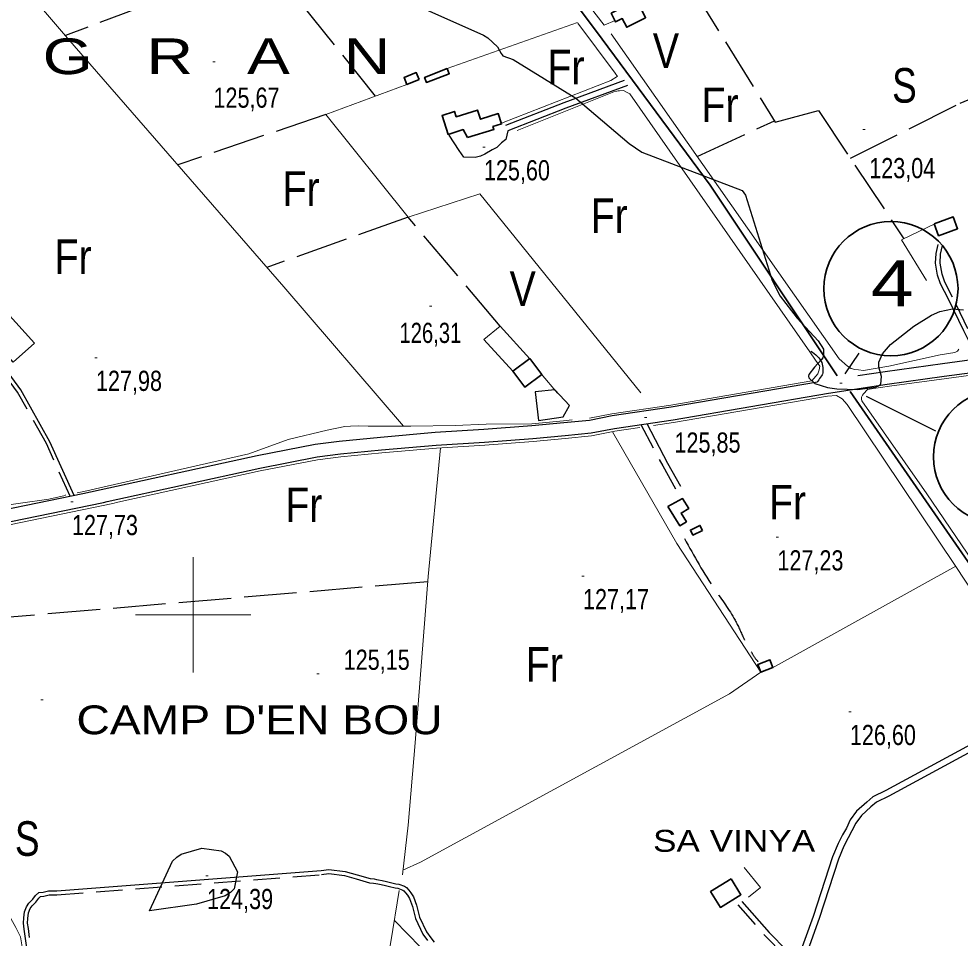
# Model space of a CAD drawing. Extents: x 483847 to 488453, y 4383581 to 4386795.
# Drawn here: x 486424.4 to 486832.5, y 4384859.8 to 4385258.4 of the extents above; entities that cross this region are included whole.
import ezdxf
from ezdxf.enums import TextEntityAlignment as Align

# ---------------------------------------------------------------- set-up
doc = ezdxf.new("R2010")
doc.units = 0
doc.header["$LTSCALE"] = 3.8
doc.linetypes.add('LONG_DASHED', pattern=[7.5, 6, -1.5])
doc.linetypes.add('MEDIUM_DASHED', pattern=[4.5, 3, -1.5])
for name, color, linetype, lineweight in [('1', 7, 'Continuous', 13), ('13', 7, 'Continuous', 25), ('21', 7, 'Continuous', 25), ('25', 7, 'LONG_DASHED', 25), ('36', 7, 'Continuous', 25), ('38', 7, 'Continuous', 25), ('47', 7, 'Continuous', 35), ('51', 7, 'Continuous', 13), ('6', 7, 'Continuous', 35), ('7', 7, 'Continuous', 13), ('8', 7, 'Continuous', 25)]:
    doc.layers.add(name, color=color, linetype=linetype, lineweight=lineweight)
doc.layers.add('31', color=7, linetype='Continuous')
doc.layers.add('5', color=7, linetype='Continuous')

msp = doc.modelspace()

# ---------------------------------------------------------------- linework, layer by layer
at = {"layer": '1'}
for p, q in [((486500, 4385025), (486500, 4384975)), ((486475, 4385000), (486525, 4385000))]:
    msp.add_line(p, q, dxfattribs=at)
at = {"layer": '21'}
for points in [[(486422.01, 4385109.58), (486409.88, 4385123.11), (486419.02, 4385131.31), (486431.15, 4385117.78)], [(486649.69, 4385084.33), (486660.44, 4385085.83), (486663.06, 4385090.75), (486656.7, 4385097.52), (486648.29, 4385096.74)]]:
    msp.add_lwpolyline(points, close=True, dxfattribs=at)
at = {"layer": '25'}
for p, q in [((486534.31, 4385284.81), (486444.57, 4385251.17)), ((486557.49, 4385216.97), (486493.3, 4385195.11)), ((486718.49, 4385198.73), (486751.94, 4385214.25)), ((486593.17, 4385172.49), (486531.98, 4385150.63)), ((486633.09, 4385125.17), (486593.17, 4385172.49)), ((486601.64, 4385014.36), (486335.46, 4384991.81))]:
    msp.add_line(p, q, dxfattribs=at)
for points in [[(486579.03, 4385224.91), (486531.89, 4385283.89), (486621.26, 4385317.93)], [(486715.71, 4385272.63), (486752.31, 4385213.65), (486771.07, 4385218.71), (486808.04, 4385163.09)], [(486784.88, 4385197.95), (486832.42, 4385221.88), (486887.14, 4385244.21), (486926.28, 4385257.91), (486977.19, 4385187.02), (487015.51, 4385200.95), (487056.56, 4385139.53)]]:
    msp.add_lwpolyline(points, dxfattribs=at)
at = {"layer": '36'}
for points in [[(486788.13, 4385103.8), (486799.99, 4385105.59), (486824.76, 4385108.99), (486852.42, 4385112.73), (486879.93, 4385115.94), (486915.02, 4385120.69), (486950.06, 4385124.99), (487008.15, 4385132.49), (487066.94, 4385140.05), (487152.14, 4385151.05), (487219.98, 4385161.17), (487294.79, 4385172.63), (487350, 4385181.14), (487422.16, 4385191.98), (487448.32, 4385195.53)], [(486398.31, 4385035.88), (486461.13, 4385048.69), (486462.73, 4385049.14), (486528.81, 4385063.65), (486553.7, 4385068.46), (486563.83, 4385069.82), (486581.63, 4385071.52), (486605.36, 4385073.58), (486626.31, 4385074.93), (486647.28, 4385076.51), (486661.18, 4385077.81), (486672.55, 4385078.92), (486682.57, 4385080.87), (486708.05, 4385084.63), (486775.37, 4385096.2), (486800.8, 4385100.04), (486825.52, 4385103.44), (486853.12, 4385107.17)], [(486397.22, 4385041.38), (486452.17, 4385052.61), (486452.19, 4385052.58), (486527.68, 4385069.14), (486552.8, 4385074), (486563.2, 4385075.39), (486581.12, 4385077.1), (486604.95, 4385079.16), (486625.92, 4385080.52), (486646.81, 4385082.09), (486660.65, 4385083.38), (486671.74, 4385084.47), (486681.62, 4385086.4), (486707.17, 4385090.17), (486770.61, 4385101.07)]]:
    msp.add_lwpolyline(points, dxfattribs=at)
msp.add_spline([(486767.68, 4385114.39), (486772.5, 4385109.36), (486772.99, 4385106.58), (486772.97, 4385105.38), (486772.81, 4385104.41), (486772.42, 4385103.66), (486770.74, 4385101.28), (486770.61, 4385101.07)], degree=3, dxfattribs=at)
at = {"layer": '38'}
for points in [[(486686.81, 4385231.67), (486660.69, 4385221.99), (486635.41, 4385212.15)], [(486688.29, 4385229.55), (486661.57, 4385219.65), (486636.32, 4385209.82)], [(486636.32, 4385209.82), (486635.52, 4385206.1), (486633.63, 4385204.7), (486631.65, 4385202.7), (486629.6, 4385201.6), (486626.43, 4385199.7), (486624.61, 4385198.82), (486622.28, 4385198.26), (486617.33, 4385198.4), (486615.34, 4385201.28), (486611.01, 4385207.95)], [(486840.18, 4385111.08), (486834.13, 4385123.12), (486827.44, 4385136.94), (486824.03, 4385143.52), (486822.72, 4385147.23), (486821.84, 4385152.44), (486822.06, 4385156.73), (486822.98, 4385160.61)], [(486448.36, 4385051.83), (486437.86, 4385075.04), (486425.24, 4385097.52), (486412.29, 4385115.2), (486404.5, 4385123.67), (486402.79, 4385126.68)], [(486696.61, 4385082.94), (486705.66, 4385065.74), (486711.28, 4385055.77)], [(486871.62, 4384959.34), (486801.55, 4384921.35), (486796.15, 4384918.79), (486793.78, 4384916.77), (486789.64, 4384913.03), (486787.19, 4384909.74), (486785.59, 4384906.31), (486783.89, 4384903.32), (486782.07, 4384899.65), (486779.7, 4384894.15), (486771.31, 4384868.35), (486749.34, 4384806.96), (486719.71, 4384723.87), (486691.28, 4384645.79), (486672.37, 4384593.39), (486657.19, 4384549.7), (486638.22, 4384498.21), (486619.96, 4384444), (486590.17, 4384360.22), (486574.09, 4384315.2)], [(486870.18, 4384961.68), (486800.3, 4384923.8), (486794.64, 4384921.12), (486791.97, 4384918.84), (486787.59, 4384914.89), (486784.82, 4384911.16), (486783.15, 4384907.57), (486781.47, 4384904.61), (486779.57, 4384900.81), (486777.13, 4384895.12), (486768.71, 4384869.24), (486762.14, 4384850.9)], [(486444.14, 4384741.23), (486426.75, 4384863.74), (486426.41, 4384866.31), (486426.52, 4384868.59), (486426.87, 4384871.24), (486427.66, 4384873.46), (486428.76, 4384875.06), (486430.44, 4384876.69), (486431.67, 4384878.33), (486433.02, 4384879.57), (486434.96, 4384879.84), (486437.31, 4384880.35), (486440.85, 4384880.37), (486555.4, 4384889.23), (486558.8, 4384889.64), (486565.88, 4384888.7), (486571.13, 4384887.27), (486576.72, 4384885.63), (486578.43, 4384885.53), (486579.49, 4384885.28), (486580.39, 4384885.12), (486581.89, 4384884.87), (486583.77, 4384884.39), (486585.48, 4384883.92), (486587.87, 4384883.43), (486589.16, 4384883.19), (486591.66, 4384882.32), (486592.53, 4384881.74), (486593.43, 4384880.66), (486594.4, 4384879.51), (486595.45, 4384877.81), (486596.83, 4384874.15), (486598.04, 4384868.97), (486601.15, 4384862.51), (486603.05, 4384859.95), (486604.44, 4384858.06)], [(486737.86, 4384875.75), (486749.72, 4384862.27), (486757.33, 4384854.5), (486759.64, 4384852.87), (486760.9, 4384851.8), (486761.81, 4384851.14), (486762.14, 4384850.9)]]:
    msp.add_lwpolyline(points, dxfattribs=at)
at = {"layer": '38', "linetype": 'MEDIUM_DASHED'}
for points in [[(486842.23, 4385111.35), (486835.88, 4385123.99), (486829.18, 4385137.82), (486825.83, 4385144.3), (486824.62, 4385147.72), (486823.8, 4385152.55), (486824.01, 4385156.45), (486824.88, 4385160.16)], [(486446.65, 4385051.48), (486436.35, 4385074.27), (486423.8, 4385096.6), (486410.98, 4385114.12), (486403.12, 4385122.66), (486401.31, 4385125.85)], [(486694.06, 4385082.57), (486703.53, 4385064.58), (486709.16, 4385054.58)], [(486445.9, 4384741.62), (486428.54, 4384863.99), (486428.22, 4384866.39), (486428.32, 4384868.43), (486428.63, 4384870.82), (486429.28, 4384872.63), (486430.15, 4384873.9), (486431.79, 4384875.5), (486433.01, 4384877.11), (486433.83, 4384877.86), (486435.28, 4384878.07), (486437.5, 4384878.55), (486440.93, 4384878.57), (486555.58, 4384887.43), (486558.79, 4384887.82), (486565.53, 4384886.93), (486570.64, 4384885.54), (486576.41, 4384883.84), (486578.18, 4384883.74), (486579.13, 4384883.52), (486580.08, 4384883.35), (486581.51, 4384883.11), (486583.3, 4384882.65), (486585.06, 4384882.17), (486587.52, 4384881.67), (486588.69, 4384881.45), (486590.85, 4384880.69), (486591.31, 4384880.39), (486592.05, 4384879.5), (486592.93, 4384878.45), (486593.82, 4384877.01), (486595.1, 4384873.63), (486596.33, 4384868.37), (486599.6, 4384861.58), (486601.6, 4384858.88)], [(486736.14, 4384874.25), (486748.04, 4384860.72), (486755.84, 4384852.76), (486758.24, 4384851.06), (486759.5, 4384850), (486760.47, 4384849.3), (486761.35, 4384848.65)]]:
    msp.add_lwpolyline(points, dxfattribs=at)
at = {"layer": '38', "linetype": 'LONG_DASHED'}
msp.add_spline([(486712.96, 4385033.08), (486726.15, 4385010.9), (486734.89, 4384997.72), (486738.53, 4384990.09), (486740.21, 4384986.69), (486742.11, 4384983.59), (486744.47, 4384980.18), (486744.83, 4384979.8)], degree=3, dxfattribs=at)
at = {"layer": '47'}
for points in [[(486696.75, 4385268.7), (486681.25, 4385260.82), (486683.13, 4385257.09), (486686.02, 4385258.55), (486687.93, 4385254.76), (486696.14, 4385258.91), (486694.61, 4385261.91), (486698.89, 4385264.11)], [(486610.15, 4385236.85), (486600.27, 4385233.06), (486601.13, 4385230.83), (486611.01, 4385234.62)], [(486597.93, 4385232.07), (486592.65, 4385229.93), (486591.41, 4385232.99), (486596.69, 4385235.13)], [(486618.88, 4385206.94), (486630.33, 4385210.52), (486629.96, 4385211.7), (486633.67, 4385212.87), (486632.26, 4385217.33), (486624.49, 4385214.87), (486623.21, 4385218.88), (486614, 4385215.95), (486613.24, 4385218.31), (486607.87, 4385216.59), (486610.52, 4385208.31), (486617.09, 4385210.44)], [(486821.24, 4385169.52), (486829.46, 4385172.54), (486831.34, 4385167.42), (486823.12, 4385164.4)], [(486645.94, 4385111.1), (486651.07, 4385104.16), (486643.74, 4385098.75), (486638.61, 4385105.69)], [(486705.8, 4385047.06), (486710.94, 4385038.66), (486713.79, 4385040.41), (486711.49, 4385044.15), (486714.8, 4385046.18), (486712.18, 4385050.43)], [(486720.74, 4385036.57), (486716.63, 4385034.58), (486715.56, 4385036.79), (486719.67, 4385038.78)], [(486751.33, 4384977.15), (486746.09, 4384975.09), (486744.74, 4384978.52), (486749.98, 4384980.58)], [(486733.21, 4384885.57), (486724.28, 4384880.06), (486728.53, 4384873.18), (486737.46, 4384878.69)]]:
    msp.add_lwpolyline(points, close=True, dxfattribs=at)
at = {"layer": '51'}
for p, q in [((486610.15, 4385236.85), (486666.56, 4385256.83)), ((486657.99, 4385096.16), (486650.83, 4385104.5)), ((486751.08, 4384977.06), (486830.66, 4385021.06))]:
    msp.add_line(p, q, dxfattribs=at)
for points in [[(486682.85, 4385257.65), (486678.1, 4385255.69), (486640.68, 4385304.24), (486607.97, 4385346.36), (486584.05, 4385379.27)], [(486171.92, 4385214.4), (486206.85, 4385238.2), (486361.2, 4385348.39), (486445.48, 4385250.09), (486539.31, 4385142.19), (486591.21, 4385081.82)], [(486666.79, 4385256.51), (486682.9, 4385234.82), (486683.9, 4385233.4)], [(486681.2, 4385251.89), (486779.96, 4385111.06), (486783.66, 4385107.85), (486785.3, 4385106.85), (486786.79, 4385106.46), (486788.37, 4385106.21), (486790.61, 4385105.95), (486801.52, 4385107.9), (486823.8, 4385112.68), (486830.19, 4385113.71), (486831.4, 4385114.37), (486831.94, 4385115.26)], [(486683.86, 4385233.46), (486681.06, 4385231.71), (486633.58, 4385213.2)], [(486694.05, 4385096.23), (486624.31, 4385182.62), (486593.17, 4385172.49), (486557.49, 4385216.97), (486592.65, 4385229.93)], [(486640.46, 4385210), (486682.34, 4385226.74), (486683.7, 4385227.09), (486684.22, 4385227.23), (486684.82, 4385227.23), (486686.48, 4385227.35), (486687.89, 4385226.66), (486689.23, 4385225.96), (486767.32, 4385114.01), (486769.82, 4385110.45), (486771.58, 4385107.87), (486771.41, 4385106.3), (486770.78, 4385104.51), (486768.14, 4385101.48)], [(486821.77, 4385169.71), (486807.03, 4385162.59), (486817.96, 4385145.03)], [(486794.1, 4385097.95), (486801.86, 4385099.12), (486826.57, 4385102.52), (486854.16, 4385106.23), (486881.67, 4385109.44), (486916.78, 4385114.2), (486951.8, 4385118.5), (487008.57, 4385125.57)], [(486645.91, 4385111.08), (486633.09, 4385125.17), (486626.03, 4385119.41), (486638.61, 4385105.69)], [(486768.14, 4385101.48), (486707.04, 4385090.97), (486681.49, 4385087.2), (486671.77, 4385085.3)], [(486794.1, 4385097.95), (486792.37, 4385097.67), (486790.54, 4385095.9), (486790.09, 4385095.3), (486789.93, 4385094.93), (486789.7, 4385094.33), (486789.68, 4385093.51), (486789.9, 4385092.76), (486817.99, 4385052.43), (486848.12, 4385008.33), (486858.49, 4384993.48), (486861.43, 4384994.63)], [(486775, 4385094.84), (486708.25, 4385083.37), (486699.5, 4385082.08)], [(486775, 4385094.84), (486778.9, 4385095.16), (486781.36, 4385093.63), (486783.5, 4385091.27), (486830.67, 4385021.04), (486861.8, 4384973.54), (486864.73, 4384968.62), (486865.54, 4384967.19), (486865.53, 4384966.74), (486865.52, 4384965.99), (486865.27, 4384964.11), (486864.95, 4384962.99), (486864.56, 4384961.95), (486862.43, 4384959.5)], [(486693.56, 4385081.2), (486682.78, 4385079.61), (486672.73, 4385077.66), (486661.3, 4385076.53), (486647.38, 4385075.23), (486626.4, 4385073.64), (486605.47, 4385072.3), (486581.75, 4385070.24), (486563.98, 4385068.54), (486553.9, 4385067.2), (486529.08, 4385062.39), (486467.29, 4385048.9), (486465.09, 4385048.22), (486398.55, 4385034.62), (486354.12, 4385026.32), (486329.99, 4385022.32), (486305.78, 4385017.49), (486271.85, 4385010.99), (486247.87, 4385006.22), (486220.98, 4385002.57), (486184.88, 4384997.68), (486142, 4384991.9), (486139.1, 4384991.63)], [(486524.09, 4385069.85), (486541.21, 4385076.06), (486558.08, 4385080.09), (486565.76, 4385081.63), (486568.24, 4385081.82), (486571.54, 4385081.93), (486575.81, 4385081.87), (486578.82, 4385081.82), (486582.19, 4385081.85), (486584.74, 4385081.81), (486594.35, 4385081.83), (486613.56, 4385082.15), (486627, 4385082.63)], [(486627, 4385082.63), (486646.74, 4385082.89), (486660.57, 4385084.18), (486664.27, 4385084.55)], [(486681.81, 4385079.43), (486709.7, 4385030.95), (486746.09, 4384975.09)], [(486449.74, 4385052.96), (486452.54, 4385053.52), (486452.56, 4385053.49), (486524.09, 4385069.85)], [(486590.66, 4384887.31), (486593.22, 4384908.81), (486596.28, 4384944.56), (486601.82, 4385016.66), (486607.17, 4385072.42)], [(486316.07, 4385031.79), (486354.66, 4385038.29), (486372.02, 4385040.51), (486389.63, 4385044.01), (486399.1, 4385044.7), (486412.63, 4385046.76), (486437.44, 4385050.23), (486444.45, 4385051.78), (486444.67, 4385052.08)], [(486313.49, 4385019.04), (486367.94, 4384949.03), (486393.98, 4384912.86), (486408.24, 4384892.32), (486414.81, 4384879.55), (486418.62, 4384872.51), (486423.08, 4384864.5), (486425.12, 4384860.34), (486425.88, 4384856.05), (486426.26, 4384851.25), (486433.2, 4384801.1), (486443.52, 4384720.28), (486442.73, 4384717.59), (486439.82, 4384713.13), (486437.17, 4384711.37), (486434.08, 4384710.36), (486429.06, 4384711.04), (486407.95, 4384714.34)], [(486590.89, 4384889.26), (486598.54, 4384892.82), (486732.55, 4384965.72), (486746.09, 4384975.09)], [(486738.9, 4384890.44), (486745.91, 4384881.86), (486740.67, 4384877.66)], [(486589.29, 4384880.5), (486585.74, 4384858.26), (486569.33, 4384770.93), (486562.25, 4384732.39), (486555.47, 4384688.22), (486548.63, 4384656.42), (486542.87, 4384630.84), (486533.42, 4384589.86), (486532.52, 4384589.5), (486512.19, 4384511.3), (486491.17, 4384426.66), (486479.19, 4384376.33), (486459.91, 4384297.67)], [(486587.23, 4384867.55), (486604.16, 4384850.12), (486633.69, 4384816.16), (486667.6, 4384774.25), (486710.13, 4384725.69), (486714.16, 4384719.11)]]:
    msp.add_lwpolyline(points, dxfattribs=at)
at = {"layer": '6', "lineweight": 25}
for p, q in [((486782.69, 4385104.52), (486788.71, 4385113.52)), ((486791.71, 4385094.77), (486821.77, 4385079.76))]:
    msp.add_line(p, q, dxfattribs=at)
at = {"layer": '6'}
for points in [[(486779.18, 4385103.59), (486724.1, 4385186.32), (486677.34, 4385249.63), (486584.76, 4385373.47), (486559.43, 4385406.45), (486510.37, 4385486.01), (486393.48, 4385659.09)], [(486910.49, 4384904.75), (486878.56, 4384955.88), (486847.53, 4385006.24), (486784.74, 4385096.92)]]:
    msp.add_lwpolyline(points, dxfattribs=at)
for centre in [(486802.45, 4385141.44), (486850.05, 4385068.53)]:
    msp.add_circle(centre, 29.1, dxfattribs=at)
at = {"layer": '7'}
for p, q in [((486508.47, 4385239.72), (486509.47, 4385239.72)), ((486790.33, 4385210.4), (486791.33, 4385210.4)), ((486625.52, 4385202.78), (486626.52, 4385202.78)), ((486602.4, 4385133.78), (486603.4, 4385133.78)), ((486457.33, 4385111.47), (486458.33, 4385111.47)), ((486780.28, 4385100.46), (486781.28, 4385100.46)), ((486695.65, 4385085.62), (486696.65, 4385085.62)), ((486446.91, 4385048.96), (486447.91, 4385048.96)), ((486752.76, 4385033.63), (486753.76, 4385033.63)), ((486668.48, 4385016.83), (486669.48, 4385016.83)), ((486553.59, 4384974.5), (486554.59, 4384974.5)), ((486433.97, 4384963.23), (486434.97, 4384963.23)), ((486784.17, 4384957.92), (486785.17, 4384957.92)), ((486505.51, 4384886.8), (486506.51, 4384886.8))]:
    msp.add_line(p, q, dxfattribs=at)
at = {"layer": '8'}
msp.add_lwpolyline([(486600.86, 4385262.5), (486625.79, 4385251.41), (486627.76, 4385250.21), (486631.86, 4385246.26), (486633.47, 4385243.37), (486633.87, 4385242.85), (486634.25, 4385242.44), (486638.66, 4385240.84), (486665.92, 4385224.06), (486688.96, 4385204.39), (486694.49, 4385200.56), (486738.03, 4385183.99), (486739.36, 4385181.98), (486751, 4385145.01), (486754.48, 4385138.24), (486761.82, 4385128.63), (486770.96, 4385118.81), (486773.3, 4385115.14), (486773.28, 4385112.34), (486772.92, 4385111.52), (486772.41, 4385110.67), (486769.29, 4385107.42), (486766.83, 4385104.26), (486766.73, 4385103.47), (486766.88, 4385102.72), (486769.55, 4385100.31), (486775, 4385098.61), (486779.01, 4385098.06), (486788.01, 4385097.78), (486795.78, 4385098.75), (486797.09, 4385099.3), (486798.03, 4385099.97), (486798.38, 4385103.42), (486797.2, 4385107.51), (486797.18, 4385108.59), (486797.29, 4385109.64), (486798.78, 4385113.24), (486802.3, 4385117.17), (486812.41, 4385125.18), (486820.04, 4385129.92), (486823.67, 4385131.55), (486829.14, 4385132.69), (486833.97, 4385132.28)], dxfattribs=at)
msp.add_lwpolyline([(486481.11, 4384871.71), (486491, 4384893.24), (486492.83, 4384894.89), (486494.84, 4384896.26), (486503.68, 4384898.8), (486512.18, 4384897.63), (486513.98, 4384896.66), (486515.55, 4384895.41), (486519.2, 4384888.59), (486517.76, 4384881.19), (486516.12, 4384879.58), (486513.92, 4384878.16), (486501.49, 4384874.63)], close=True, dxfattribs=at)

# ---------------------------------------------------------------- texts
at = {"layer": '13', "width": 1.25}
msp.add_text('4', height=20, dxfattribs=at).set_placement((486803.07, 4385133.78), align=Align.CENTER)
at = {"layer": '31'}
for s, width, p in [('V', 0.85, (486704.93, 4385237.09)), ('Fr', 0.85, (486661.59, 4385230.06)), ('S', 0.8, (486808.32, 4385222.08)), ('Fr', 0.85, (486728.36, 4385213.65)), ('Fr', 0.85, (486546.79, 4385177.32)), ('Fr', 0.85, (486680.33, 4385165.6)), ('Fr', 0.85, (486447.95, 4385147.79)), ('V', 0.85, (486642.84, 4385133.96)), ('Fr', 0.85, (486757.64, 4385041.38)), ('Fr', 0.85, (486547.96, 4385040.2)), ('Fr', 0.85, (486652.21, 4384971.06)), ('S', 0.8, (486428.05, 4384895.52))]:
    msp.add_text(s, height=15, dxfattribs=dict(at, width=width)).set_placement(p, align=Align.CENTER)
at = {"layer": '5', "width": 1.35}
msp.add_text('C   A   M   P       G   R   A   N', height=15.49, dxfattribs=at).set_placement((486585.42, 4385234.45), align=Align.RIGHT)
at = {"layer": '5', "width": 1.2}
for s, height, p in [("CAMP D'EN BOU", 12.5, (486449.37, 4384948.24)), ('SA VINYA', 9.5, (486699.34, 4384897.28))]:
    msp.add_text(s, height=height, dxfattribs=at).set_placement(p)
at = {"layer": '7'}
for s, width, p in [('125,67', 0.8, (486508.78, 4385219.89)), ('125,60', 0.8, (486626.02, 4385188.41)), ('123,04', 0.8, (486793.06, 4385189.34)), ('126,31', 0.75, (486589.39, 4385117.9)), ('127,98', 0.8, (486457.83, 4385097.1)), ('125,85', 0.8, (486708.63, 4385070.35)), ('127,73', 0.8, (486447.41, 4385034.59)), ('127,23', 0.8, (486753.26, 4385019.26)), ('127,17', 0.8, (486668.98, 4385002.46)), ('125,15', 0.8, (486565.23, 4384976.18)), ('126,60', 0.8, (486784.67, 4384943.55)), ('124,39', 0.8, (486506.01, 4384872.43))]:
    msp.add_text(s, height=8.75, dxfattribs=dict(at, width=width)).set_placement(p)

doc.saveas('drawing.dxf')
